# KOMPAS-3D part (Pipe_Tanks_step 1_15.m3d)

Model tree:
1. X Axis
2. Y Axis
3. Z Axis  (labels: Bend 90 Dn 50; Pipe Dn 50; C:\Program Files\ASCON\KOMPAS-3D V10\Sys\graphic.lyt; Pipe_Tanks_step 1_15.m3d)
     Òîëùèíà ñòåíêè 1 = 1

Referenced files in C:\Documents and Settings\kashirsky\Мои документы\Camtasia Studio\Pipelines3D\Tanks\: Tanks_step 1.a3d, Tanks_step 1.spw
Referenced files in C:\Documents and Settings\kashirsky\Мои документы\Camtasia Studio\Pipelines3D\Tanks\Tanks_step 1_Pipes\: Pipe_Tanks_step 1_15.m3d
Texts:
  Pipe Dn 50
  Steel ASTM A295
  Three Point Plane
  Plane at Angle
  Line and Point Plane
  Axis through Two Vertices
  Axis of Feature
  Axis of Conical Surface
  Axis through Edge
  Trim by Surface
  Trim by Sketch
  Feature with No History
  Intersection Axis of Two Planes
  Two Line Plane
  Line and Face Plane
  Bend by line
  Hole in sheet body
  Cut in sheet body
  Point in CM
  Linear Dimension from Line to Point
  Surface Finish Symbol
  Geometric Tolerance Symbol
  Leader #1
  Leader #2
  Leader #3
  Shape Deviations and Datum
  Node point number
  Mark of coordination axis
  Node point designation
  Mark/Reference designation with leader
  Mark/reference designation on line
  Mark/Reference designation without leader
  Bend 90 Dn 50
  Plane of section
